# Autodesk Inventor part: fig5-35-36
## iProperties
Shininess: 77.0
Angle Display Precision: 2
Document Length Units: 11269
Document Angle Units: 11279
Document Time Units: 11290
Document Mass Units: 11283
Document Length Units Precision: 3
Document Angle Units Precision: 2
Created: 2001-12
Part Number: fig5-35-36
Document SubType Name: Modeling
Designer: Renu Muthoo
Density: 1 g/cm^3
Density: 0.0
Volumn: 0.0
Area: 0.0
PropertySet Name: Model Information
Control State: 0
Master: False
Checked Out: False
Author: Renu Muthoo
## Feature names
1. Extrusion1
2. Extrusion3
3. Chamfer5
